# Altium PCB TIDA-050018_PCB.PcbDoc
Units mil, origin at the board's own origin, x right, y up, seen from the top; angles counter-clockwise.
Board outline 2547.53 x 1907.53 mil, 2 copper layers (Top Layer, Bottom Layer), stack 62 mil thick; 19 components, 10 nets, 73 pads, 3 vias.
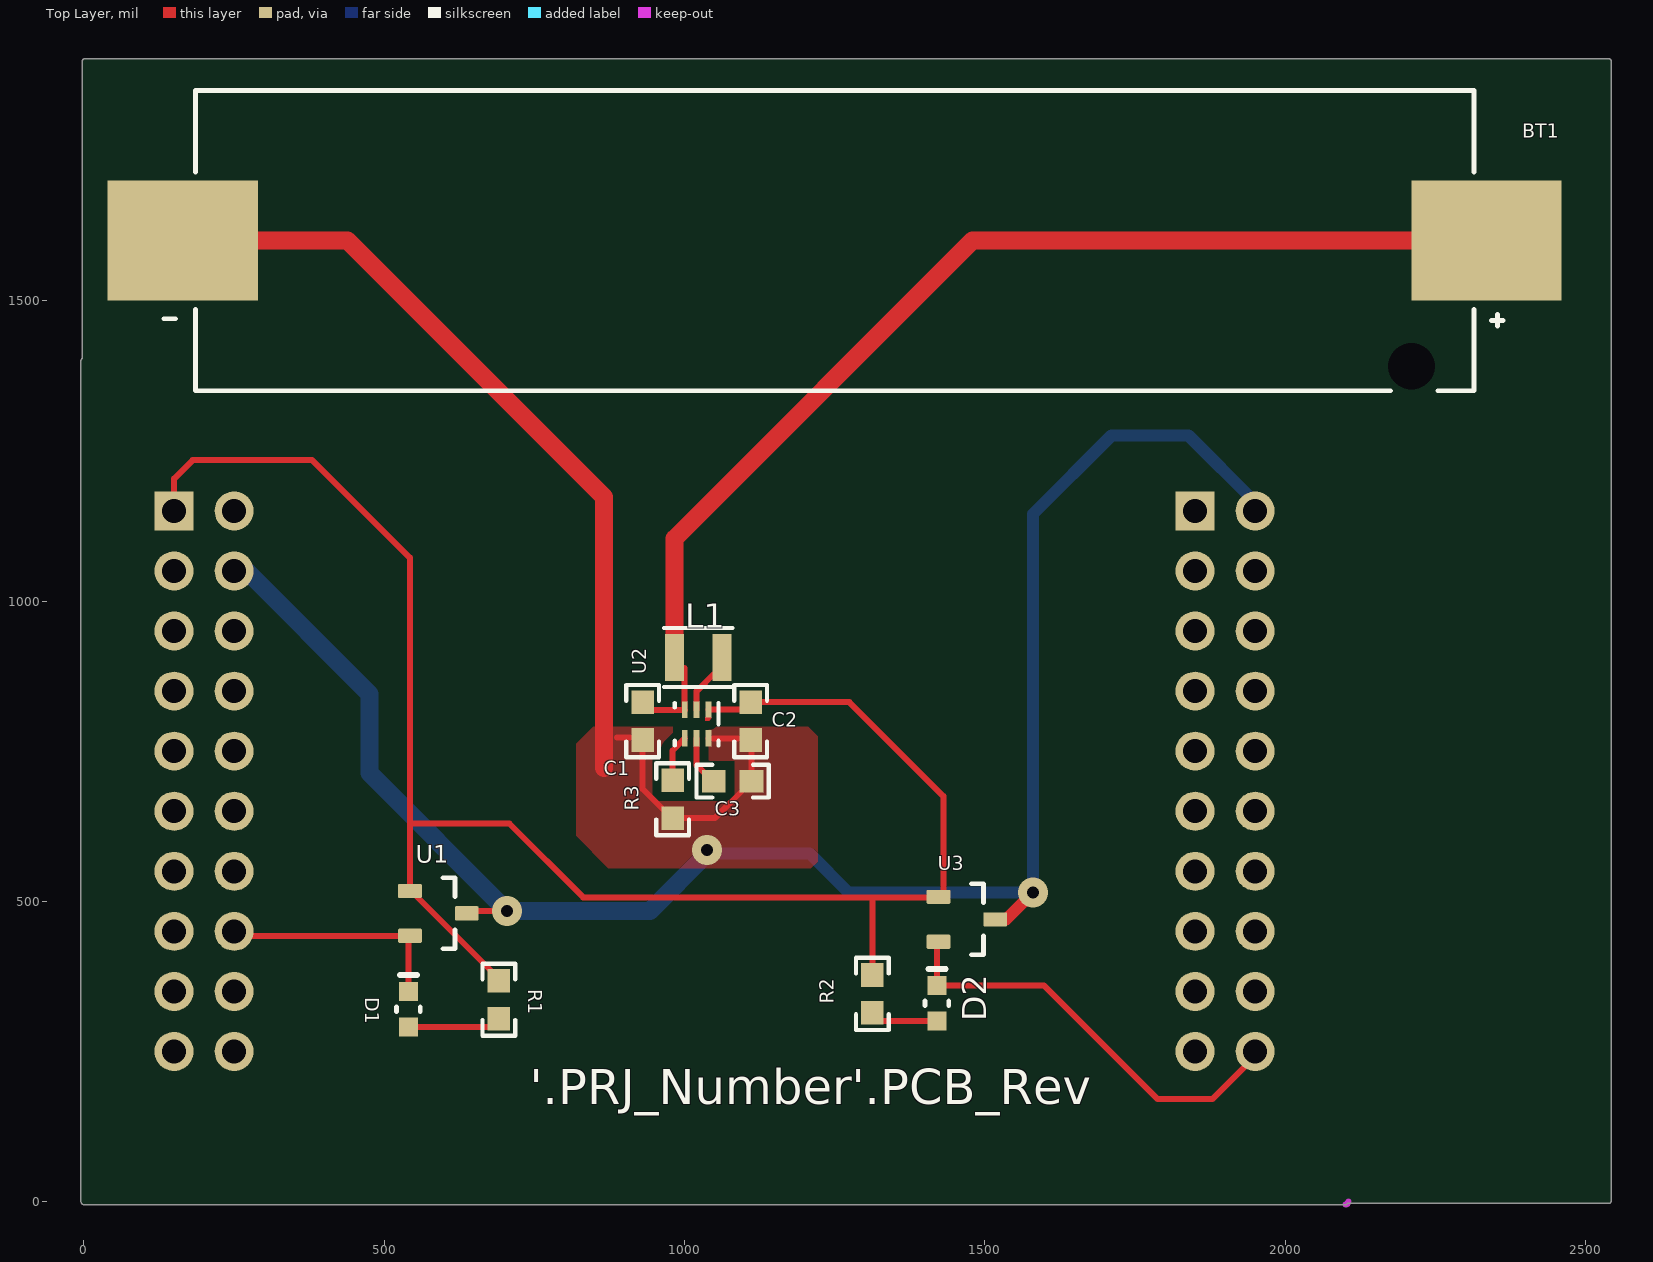
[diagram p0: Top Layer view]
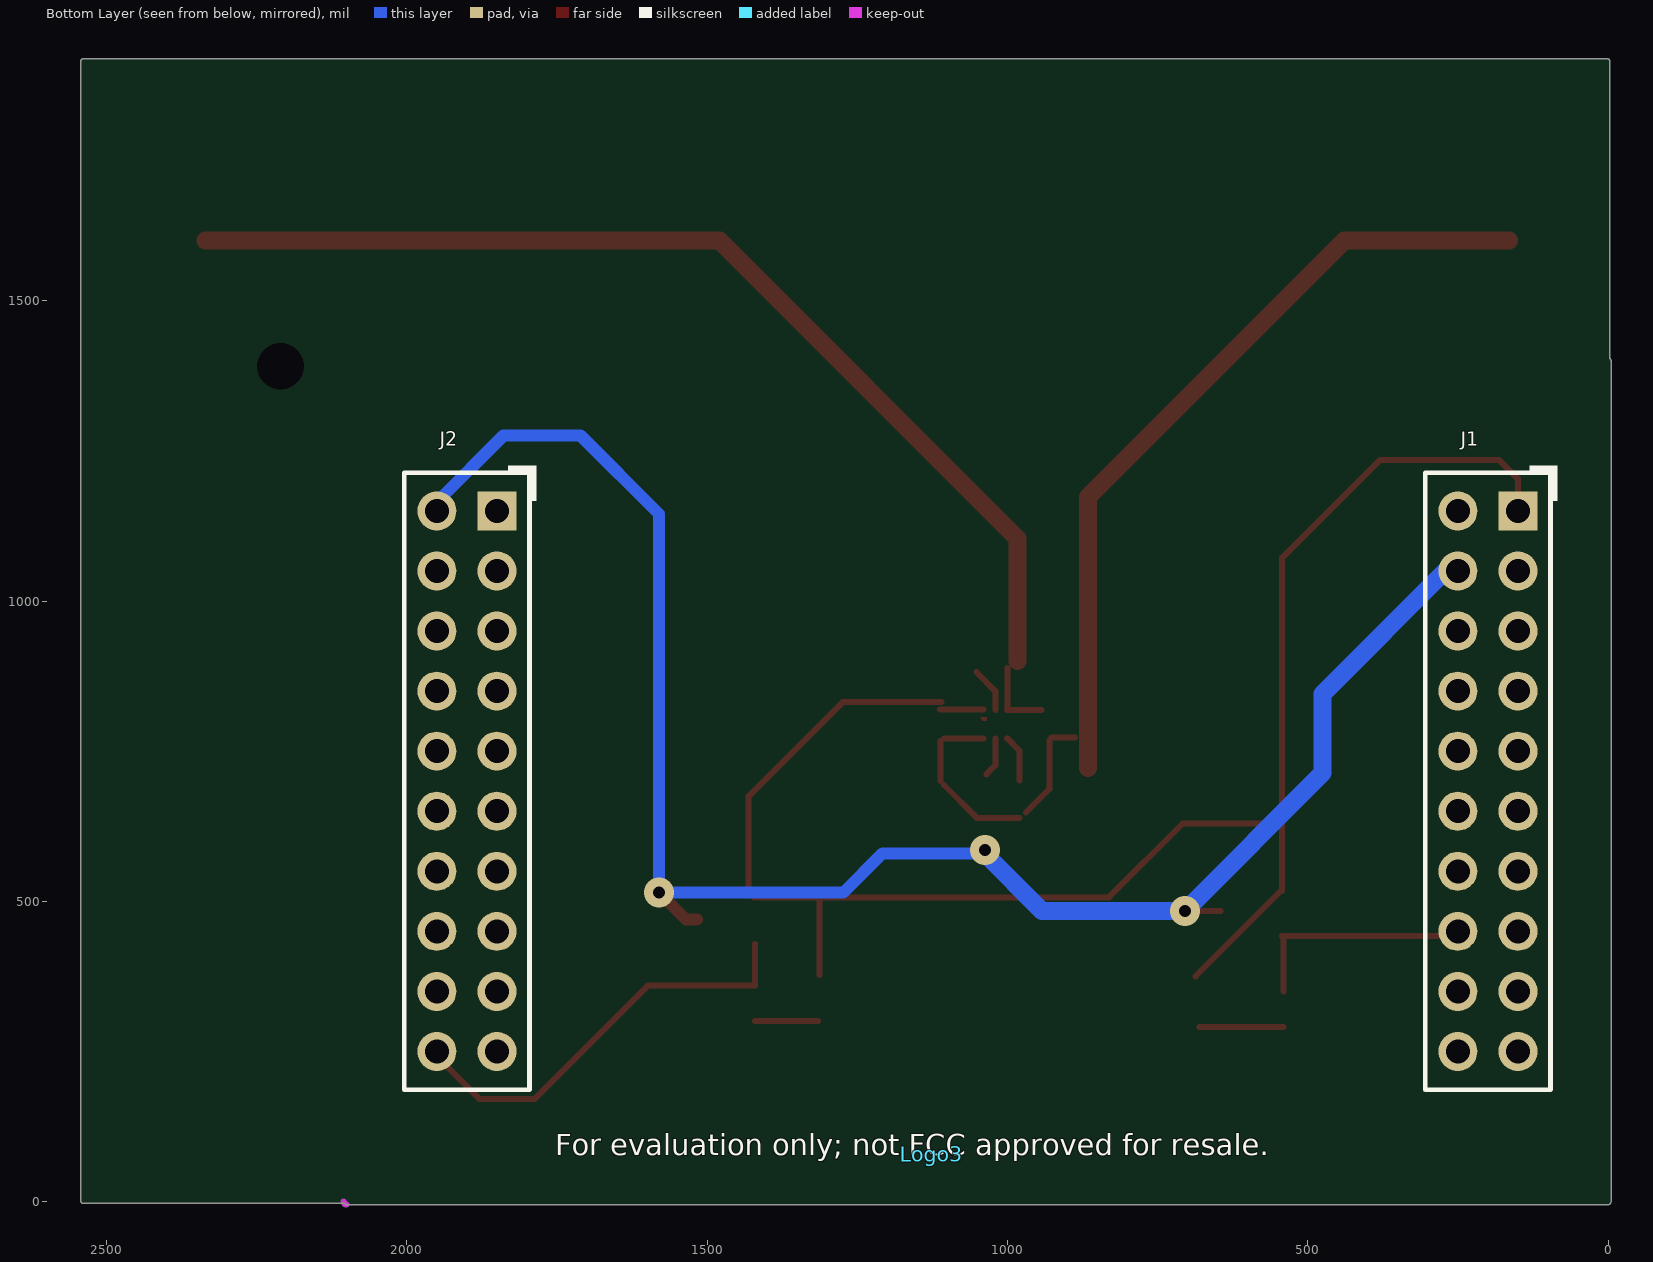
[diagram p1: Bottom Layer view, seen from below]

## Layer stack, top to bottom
Top Solder: solder mask 0.4, Solder Resist, Dk 3.5
Top Layer: signal copper 1.4
Dielectric1: core 59.2, FR-4, Dk 4.8
Bottom Layer: signal copper 1.4
Bottom Solder: solder mask 0.4, Solder Resist, Dk 3.5

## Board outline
-5.01,0 -5.01,1400 cw(c0,1400) -2.51,1404.34 -2.51,1900 cw(c0,1900) 0,1902.51 2540,1902.51 cw(c2540,1900) 2542.51,1900 2542.51,0 cw(c2540,0) 2540,-2.52 2104.34,-2.52 cw(c2100,0) 2100,-5.02 0,-5.02 cw(c0,0)

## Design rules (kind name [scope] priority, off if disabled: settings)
AcuteAngle [All] p1: minimum=4.50000000000000E+0001 checktracksonly=FALSE
AssemblyTestPointUsage [All] p1: valid=2
BoardOutlineClearance BoardOutlineClearance_MountingHoles [OnCopper and InComponentClass('Mounting Holes')] p1: gap=40 ignorepadtopadclearanceinfootprint=FALSE
BoardOutlineClearance BoardOutlineClearance_Poly [OnCopper and InPoly] p2: gap=25 ignorepadtopadclearanceinfootprint=FALSE
BoardOutlineClearance [OnCopper and Not InComponentClass('Logo') and not InComponentClass('FiducialMark') and not InRegion(1000,500,4000,800)] p3: gap=25 ignorepadtopadclearanceinfootprint=FALSE
Clearance Clearance_Keepouts [((IsTrack Or IsArc) And Not InPoly) And IsFree and IsKeepOut vs ((IsTrack Or IsArc) And Not InPoly) And IsFree and IsKeepOut] p1: gap=0 ignorepadtopadclearanceinfootprint=FALSE
Clearance Clearance_Poly [InPolygon] p2: gap=15 ignorepadtopadclearanceinfootprint=FALSE except(0: Arc-Hole Track-Hole SMDPad-Hole THPad-Hole Via-Hole Fill-Hole Poly-Hole Region-Hole Text-Hole; 10: THPad-Poly)
Clearance [All] p3: gap=3 ignorepadtopadclearanceinfootprint=FALSE
ComponentClearance ComponentClearance_MountingHoles_FiducialMarks [InComponentClass('Mounting Holes') vs InComponentClass('FiducialMark')] p1: gap=50 collisioncheckmode=3 verticalgap=10 showdistances=FALSE
ComponentClearance ComponentClearance_Shunt [InComponentClass('Header') vs InComponentClass('Shunt')] p2: gap=0 collisioncheckmode=3 verticalgap=0 showdistances=FALSE
ComponentClearance ComponentClearance_Logo [InComponentClass('Logo')] p3: gap=0 collisioncheckmode=3 verticalgap=0 showdistances=FALSE
ComponentClearance ComponentClearance_ScrewToNut [(HasFootprint('NY PMS 440 0025 PH')) vs (HasFootprint('Keystone_1902C'))] p4: gap=5 collisioncheckmode=3 verticalgap=10 showdistances=FALSE
ComponentClearance ComponentClearance_MountingHoles [InComponentClass('Mounting Holes')] p5: gap=250 collisioncheckmode=3 verticalgap=100000 showdistances=FALSE
ComponentClearance ComponentClearance_SmallPassives [HasFootprint('0201*') or HasFootprint('0402*') or HasFootprint('0508') or HasFootprint('0603*') or HasFootprint('0612') or HasFootprint('0805*') or HasFootprint('0815*') or HasFootprint('0830*') or HasFootprint('1206*') or HasFootprint('1210*') or HasFootprint('1808*') or HasFootprint('1812*') or HasFootprint('1825*') or HasFootprint('2010*') or HasFootprint('2220*') or HasFootprint('2225*') or HasFootprint('2512*') or HasFootprint('2728*') or HasFootprint('3518*') vs HasFootprint('0201*') or HasFootprint('0402*') or HasFootprint('0508') or HasFootprint('0603*') or HasFootprint('0612') or HasFootprint('0805*') or HasFootprint('0815*') or HasFootprint('0830*') or HasFootprint('1206*') or HasFootprint('1210*') or HasFootprint('1808*') or HasFootprint('1812*') or HasFootprint('1825*') or HasFootprint('2010*') or HasFootprint('2220*') or HasFootprint('2225*') or HasFootprint('2512*') or HasFootprint('2728*') or HasFootprint('3518*')] p6: gap=14.96 collisioncheckmode=3 verticalgap=10 showdistances=FALSE
ComponentClearance ComponentClearance_THtoSMT [IsThruComponent vs IsSMTComponent] p7: gap=40 collisioncheckmode=3 verticalgap=30 showdistances=FALSE
ComponentClearance ComponentClearance_THtoTH [IsThruComponent vs IsThruComponent] p8: gap=30 collisioncheckmode=3 verticalgap=30 showdistances=FALSE
ComponentClearance [All] p9: gap=30 collisioncheckmode=3 verticalgap=10 showdistances=FALSE
DiffPairsRouting [All] p1: maxlimit=100 minlimit=10 mostfreqgap=10 toplayer_minwidth=15 toplayer_maxwidth=15 toplayer_prefwidth=15 bottomlayer_minwidth=15 bottomlayer_maxwidth=15 bottomlayer_prefwidth=15 maxuncoupledlength=1000
FabricationTestPointUsage TestPointUsage [All] p1: valid=2 allowmultiple=FALSE
FabricationTestpoint Testpoint [All] p1: side=3 testpointundercomponent=TRUE minsize=40 maxsize=100 preferedsize=60 minholesize=0 maxholesize=40 preferedholesize=32 testpointgrid=1 allowsidetop=TRUE allowsidebottom=TRUE usegrid=TRUE gridtolerance=0.01
FanoutControl Fanout_LCC [IsLCC] p1: bgadir=Out bgaviamode=Centered fanoutstyle=Auto fanoutdirection=Alternating viagrid=1 // Fanout_LCC (Default Rule)
FanoutControl Fanout_BGA [IsBGA] p2: bgadir=Out bgaviamode=Centered fanoutstyle=Auto fanoutdirection=Alternating viagrid=1 // Fanout_BGA (Default Rule)
FanoutControl Fanout_Default [All] p4: bgadir=Out bgaviamode=Centered fanoutstyle=Auto fanoutdirection=Alternating viagrid=1 // Fanout_Default (Default Rule)
FanoutControl Fanout_Small [(CompPinCount < 5)] p5: bgadir=Out bgaviamode=Centered fanoutstyle=Auto fanoutdirection=OutThenIn viagrid=1 // Fanout_Small (Default Rule)
HoleSize [All] p1: absolutevalues=TRUE maxlimit=251 minlimit=7.87 maxpercent=80.000 minpercent=20.000
MinimumAnnularRing MinimumAnnularRing_ThermalPadVias [IsVia and InAnyComponent] p1: minimumring=5.91
MinimumAnnularRing [All] p2: minimumring=6
MinimumSolderMaskSliver MinimumSolderMaskSliver_Logo [InComponentClass('Logo') vs InComponentClass('Logo')] p1: minsoldermaskwidth=0.7
MinimumSolderMaskSliver [All] p2: minsoldermaskwidth=3.94
PlaneConnect [All] p1: planeconnectstyle=Relief reliefexpansion=10 reliefentries=4 reliefconductorwidth=10 reliefairgap=10
PolygonConnect PolygonConnect_1 [InThruComponent vs ispoly] p1: connectstyle=Relief reliefconductorwidth=15 reliefentries=4 polygonreliefangle="90 Angle" airgapwidth=15
PolygonConnect [All] p2: connectstyle=Direct reliefconductorwidth=10 reliefentries=4 polygonreliefangle="90 Angle" airgapwidth=10
RoutingVias ThermalPadVias [IsVia and InAnyComponent] p1: holewidth=7.87 width=19.68 viastyle="Through Hole" minholewidth=7.87 minwidth=19.68 maxholewidth=12.99 maxwidth=23.62
RoutingVias [All] p2: holewidth=10 width=26 viastyle="Through Hole" minholewidth=7.87 minwidth=22 maxholewidth=40 maxwidth=65
SilkToBoardRegionClearance [Not ((IsComment or IsDesignator) And (Hide <> 'False')) and not InRegion(1000,500,4000,800)] p1:
SilkToSilkClearance SilkToSilkClearance_Pb-FreeLogo [(HasFootprint('Pb-Free_Overlay_Medium') OR HasFootprint('Pb-Free_Overlay_Small')) vs (HasFootprint('Pb-Free_Overlay_Medium') OR HasFootprint('Pb-Free_Overlay_Small'))] p1: silktosilkclearance=0
SilkToSilkClearance [All] p2: silktosilkclearance=4
SilkToSolderMaskClearance SilkToComponentPadClearance [IsPad and InAnycomponent] p1: minsilkscreentomaskgap=5 clearancetoexposedcopper=TRUE
SilkToSolderMaskClearance "Silk to Solder Mask Opening" [All] p2: minsilkscreentomaskgap=4 clearancetoexposedcopper=FALSE
SolderMaskExpansion [All] p1: expansion=1.97
Width [All] p1: maxlimit=100 minlimit=7.8 preferedwidth=10 checkconnectedcopper=TRUE
15 further rules are at their usual default settings.

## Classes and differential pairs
component class AssemblyNote: ZZ1 ZZ2 ZZ3 ZZ4
component class TIDA-050018_Main: BT1 C1 C2 C3 D1 D2 J1 J2 L1 R1 R2 R3 U1 U2 U3
component class TIDA-050018_Hardware: !PCB1 Logo3 ZZ1 ZZ2 ZZ3

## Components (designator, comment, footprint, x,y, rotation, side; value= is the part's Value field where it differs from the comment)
BT1 "1020" Keystone_1020 1250,1600 r180 top
C1 "GRM188R60J106ME47D" 0603 930,800 r270 top value=10uF
C2 "GRM188R60J106ME47D" 0603 1110,800 r270 top value=10uF
C3 "GRM188R60J106ME47D" 0603 1080,700 r0 top value=10uF
D1 "LS L29K-G1J2-1-Z" "LS L29K_Red" 540,320 r90 top value=Red
D2 "LS L29K-G1J2-1-Z" "LS L29K_Red" 1420,330 r90 top value=Red
J1 "PPPC102LFBN-RC" Sullins_PPPC102LFBN-RC 200,700 r90 bottom
J2 "PPPC102LFBN-RC" Sullins_PPPC102LFBN-RC 1900,700 r90 bottom
L1 "1239AS-H-4R7M=P2" DFE252012C 1022.64,905.96 r0 top value=4.7uH
Logo3 "FCC disclaimer" FCC_disclaimer 1126.08,79.23 r180 bottom
R1 "RC0603FR-072K21L" 0603 690.7,336.25 r270 top value=2.21k
R2 "RC0603FR-072K21L" 0603 1312.77,345.96 r270 top value=2.21k
R3 "RC0603FR-072K21L" 0603 980,670 r90 top value=2.21k
U1 "DRV5032FBDBZR" DBZ0003A_N 590,480 r0 top
U2 "TPS610985DSER" DSE0006A 1020,795 r270 top
U3 "DRV5032FBDBZR" DBZ0003A_N 1470,470 r0 top
ZZ1 "These assemblies are ESD sensitive, ESD precautions shall be observed." AssemblyNote 70.98,3170.1 r0 top
ZZ2 "These assemblies must be clean and free from flux and all contaminants. Use of no clean flux is not acceptable." AssemblyNote 65.49,3032.88 r0 top
ZZ3 "These assemblies must comply with workmanship standards IPC-A-610 Class 2, unless otherwise specified." AssemblyNote 64.01,2902.93 r0 top

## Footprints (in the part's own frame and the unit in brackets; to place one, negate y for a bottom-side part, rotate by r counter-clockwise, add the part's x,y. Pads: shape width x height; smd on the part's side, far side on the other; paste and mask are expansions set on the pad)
0603 [mm] "0603 from SM-752 data"
  rect 1x0.95 smd: 1(-0.8,0) 2(0.8,0)
  silkscreen extent -1.52,-0.69 1.52,0.69, body extent -0.87,-0.47 0.87,0.47, height 1
AssemblyNote [mil] "Assembly Note"
DBZ0003A_N [mm] "SOT23, 3-Leads, Body 2.9x1.3mm, Pitch 0.95mm, Lead Span 2.4mm, IPC Medium Density"
  rrect17% 1x0.6 smd: 1(-1.2,0.95) 2(-1.2,-0.95) 3(1.2,0)
  silkscreen extent 0.2,-1.5 0.7,1.5, body extent -1.26,-1.46 1.26,1.46, height 0.98
DFE252012C [mm] "Toko"
  rect 0.8x2 smd: 1(-1,0) 2(1,0)
  silkscreen extent -1.45,-1.25 1.45,1.25, body extent -1.35,-1.1 1.35,1.1, height 1.2
DSE0006A [mm] "TI recommended land pattern"
  rect 0.66x0.25 smd: 1(-0.62,0.5)
  rect 0.7x0.25 smd: 2(-0.6,0) 3(-0.6,-0.5) 4(0.6,-0.5) 5(0.6,0) 6(0.6,0.5)
  Top Layer region: -0.3,0.625 -0.25,0.625 -0.15,0.525 -0.15,0.375 -0.3,0.375
  silkscreen extent -0.9,-0.92 0.9,0.92, body extent -0.77,-0.77 0.77,0.77, height 0.8
FCC_disclaimer [mil]
Keystone_1020 [mm] "HOLDER BATTERY AAA, SMT"
  rect 6.35x5.08 smd: 1(-27.57,0) 2(27.57,0)
  rect 0x0 hole 1.98 unplated: ALIGN(-24.395,5.31)
  silkscreen extent -28.28,-6.35 28.38,6.35, body extent -30.76,-6.35 30.75,6.35, height 11.27
"LS L29K_Red" [mm] "SMD, 2-Leads, Body 1.3x0.8mm"
  rect 0.8x0.8 smd paste-0.4: 1(-0.75,0) 2(0.75,0)
  silkscreen extent -0.1,-0.5 1.45,0.5, body extent -0.9,-0.45 0.9,0.45, height 0.67
Sullins_PPPC102LFBN-RC [mil] "Sullins"
  rect 65x65 hole 40: 1(450,-50)
  round 65 hole 40: 2(450,50) 3(350,-50) 4(350,50) 5(250,-50) 6(250,50) 7(150,-50) 8(150,50) 9(50,-50) 10(50,50) 11(-50,-50) 12(-50,50) 13(-150,-50) 14(-150,50) 15(-250,-50) 16(-250,50) 17(-350,-50) 18(-350,50) 19(-450,-50) 20(-450,50)
  silkscreen extent -514,-116 526,104, body extent -514,-104 514,104, height 335

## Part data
BT1: library part CMP-0003908-1, "HOLDER BATTERY AAA, SMT", Manufacturer=Keystone, Supplier Part Number 1=36-1020-ND
C1 C2 C3: library part CMP-0007303-5, "CAP, CERM, 10 uF, 6.3 V, +/- 20%, X5R, 0603", Cap_Case=0603, Manufacturer=MuRata, Supplier Part Number 1=490-3896-1-ND, TempCo=X5R, Tolerance_%=20%, Value1="0.009 ohm", Value2=6.3V, ValueDisplayed=10uF
D1 D2: library part CMP-0002902-1, "LED, Red, SMD", Color=Red, Manufacturer=OSRAM, Supplier Part Number 1=475-2506-1-ND, Value1=W, Value2=1.8V
J1 J2: library part CMP-0054642-1, "Receptacle, 100mil, 10x2, Gold, TH", Manufacturer="Sullins Connector Solutions", Supplier Part Number 1=S6106-ND
L1: library part CMP-0058899-1, "Inductor, Shielded, Ferrite, 4.7 uH, 1.3 A, 0.2 ohm, SMD", Manufacturer="MuRata Toko", PartNumber=1239AS-H-4R7M{}P2, Value1="0.2 ohm", Value2=1.3A, ValueDisplayed=4.7uH
Logo3: library part CMP-0074847-1, "FCC_disclaimer"
R1 R2 R3: library part CMP-0022984-5, "RES, 2.21 k, 1%, 0.1 W, 0603", Manufacturer=Yageo, Power_W=100mW, Supplier Part Number 1=311-2.21KHRCT-ND, TempCo="100 ppm/C", Tolerance_%=1%, Value2=0.1W, Value_Code=2k21, ValueDisplayed=2.21k
U1 U3: library part CMP-0013239-4, "Ultra-Low Power Digital-Switch Hall Effect Sensor, DBZ0003A (SOT-23-3)", Alternate Manufacturer="Texas Instruments"
U2: library part CMP-0074070-1, "Ultra-Low Quiescent Current Synchronous Boost with Integrated LDO/Load, DSE0006A (WSON-6)", Alternate Manufacturer="Texas Instruments", Alternate PartNumber=TPS610985DSET
ZZ1: library part CMP-0077236-1
ZZ2: library part CMP-0077237-1
ZZ3: library part CMP-0077238-1

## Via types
v1: diameter 50, hole 20, Top Layer to Bottom Layer, 3 vias

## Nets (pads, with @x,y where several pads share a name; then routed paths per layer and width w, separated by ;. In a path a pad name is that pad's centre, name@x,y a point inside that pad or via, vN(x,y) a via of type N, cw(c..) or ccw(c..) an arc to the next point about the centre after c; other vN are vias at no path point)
3.3V: C2.1 J1.1 R1.1 R2.1 U1.1 U2.1 U3.1 | length 2981
  Top Layer w10: J1.1 150,1203.6 181.08,1234.68 380.06,1234.68 542.5,1072.25 542.5,849.52 ; 542.76,851.6 542.76,629.6 ; R1.1@687.04,374.8 544.44,517.4 U1.1 542.76,629.6 ; U2.1 C2.1@1112.14,819.41 ; C2.1 1274.34,831.5 1430.73,675.11 U3.1@1430.73,508.99 ; R2.1 1312.77,503.69 ; 1351.1,506.15 U3.1@1421.85,506.15 ; 1365.17,506.5 831.28,506.5 708.17,629.6 542.76,629.6
GND: BT1.2 C1.2 C2.2 C3.2 J1.4 J2.2 R3.1 U1.3 U2.6 U3.3 | length 4716.6
  Top Layer w10: U1.3@645.18,484.2 v1(704.63,484.2) ; 887.41,772.9 C1.2@926.3,772.9 ; C1.2 930,687.27 R3.1@969.39,647.88 ; R3.1 1050.45,638.5 C3.2@1105.61,693.66 ; U2.6 C2.2@1105.8,771.38 ; C3.2 C2.2@1111.5,767.34
  Top Layer w20: U3.3 1535.34,470 v1@1577.18,511.83
  Top Layer w30: BT1.2 438.6,1600 865.71,1172.89 865.71,721.88
  Bottom Layer w20: v1@1039.36,579.73 1208.21,579.73 1273.43,514.51 v1(1579.86,514.51) 1579.86,1144.64 1710.78,1275.57 1838.96,1275.57 J2.2@1950.14,1164.39
  Bottom Layer w30: J1.4@266.83,1053.88 475.46,845.25 475.46,713.37 v1(704.63,484.2) 942.45,484.2 v1@1038.66,580.41
  other v1: 1037.28,585.19
HALL1: D1.2 J1.16 U1.2 | length 381.5
  Top Layer w10: J1.16@250.32,442.6 U1.2 ; D1.2 U1.2@540,438.63
HALL2: D2.2 J2.20 U3.2 | length 708.7
  Top Layer w10: U3.2@1420,429.23 D2.2 1598.53,359.53 1787.07,170.99 1879.16,170.99 J2.20@1951.1,242.93
NetBT1_1: BT1.1 C1.1 L1.1 U2.3 | length 1888.7
  Top Layer w10: C1.1@942.87,818.62 U2.3 1000,818.94 1000,888.5
  Top Layer w30: L1.1@983.54,900.19 983.54,1104.23 1479.31,1600 BT1.1
NetC3_1: C3.1 U2.5 | length 66.1
  Top Layer w10: U2.5 1020,726.57 C3.1@1035.07,711.5
NetD1_1: D1.1 R1.2 | length 140.4
  Top Layer w10: D1.1 R1.2@680.37,290.47
NetD2_1: D2.1 R2.2 | length 105
  Top Layer w10: R2.2@1315.02,300.47 D2.1
NetL1_2: L1.2 U2.2 | length 75.9
  Top Layer w10: U2.2 1020,850 L1.2@1051.5,881.5
NetR3_2: R3.2 U2.4 | length 78.3
  Top Layer w10: R3.2 980,751.06 U2.4
pads on no net: BT1.ALIGN J1.2 J1.3 J1.5 J1.6 J1.7 J1.8 J1.9 J1.10 J1.11 J1.12 J1.13 J1.14 J1.15 J1.17 J1.18 J1.19 J1.20 J2.1 J2.3 J2.4 J2.5 J2.6 J2.7 J2.8 J2.9 J2.10 J2.11 J2.12 J2.13 J2.14 J2.15 J2.16 J2.17 J2.18 J2.19

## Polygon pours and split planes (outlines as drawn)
GND on Top Layer "TOP_LAYER_GND_P002" (solid, remove dead copper, pour order 2): 1221.46,775.13 1205.64,790.96 848.02,790.96 819.46,762.41 819.46,608.95 873.27,555.14 1210.38,555.14 1221.46,566.22

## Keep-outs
Keep-Out Layer:
  lines w10: 2100,-5 ccw(c2100,0) 2105,0 cw(c2100,0) 2100,-5
  text ".Layer_Name" at 577,-858.49 h60

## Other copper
Top Layer:
  text ".Layer_Name" at 577,-858.49 h60
Bottom Layer:
  text ".Layer_Name" at 577,-858.49 h60

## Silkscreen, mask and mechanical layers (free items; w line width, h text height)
Top Overlay:
  text "'.PRJ_Number'.PCB_Rev" at 741.84,142.96 h100
  text ".Layer_Name" at 577,-858.49 h60
Bottom Overlay:
  text ".Layer_Name" at 577,-858.49 h60
Top Paste:
  text ".Layer_Name" at 577,-858.49 h60
Bottom Paste:
  text ".Layer_Name" at 577,-858.49 h60
Top Solder:
  text ".Layer_Name" at 577,-858.49 h60
  text ".Layer_Name" at 577,-858.49 h60
Bottom Solder:
  text ".Layer_Name" at 577,-858.49 h60
Drill Guide:
  text ".Layer_Name" at 577,-858.49 h60
M1 Board Outline:
  lines w5: 0,1400 0,1900 2540,1900 2540,0 2000,0
  lines w10: 0,1400 0,0 2100,0
  text ".Layer_Name" at 577,-858.49 h60
M2 Board Dimensions:
  rectangle: 125,-400 500,-275
  rectangle: 0,-275 125,-150
  lines w7: 0,-275 1000,-275 ; 125,-400 125,-150 ; 250,-400 250,-150 ; 500,-400 500,-150 ; 750,-400 750,-150 ; 0,-400 0,-150 1000,-150 1000,-400 0,-400
  text ".Layer_Name" at 577,-858.49 h60
M3 3D STEP Top:
  text ".Layer_Name" at 577,-858.49 h60
M4 3D STEP Bottom:
  text ".Layer_Name" at 577,-858.49 h60
M5 Assembly Top:
  lines w10: -292,-930.17 6308,-930.17 ; -292,-726.83 6310,-726.83 ; -292,-523.5 -292,-1133.5 3713,-1133.5 6310,-1133.5 6310,-523.5 -291.5,-523.5 -291.5,-1133.5 1284,-1133.5 ; 2173,-1133.5 2173,-523.5 ; 3440,-726.83 3440,-523.5 ; 4280,-726.83 4280,-523.5 ; 4902,-1140 4902,-937.17
  text "COMPONENTS MARKED 'DNP' SHOULD NOT BE POPULATED." at 1153.5,-318.5 h60
  text "ASSEMBLY VARIANT:" at 1153,-434 h60
  text ".VariantName" at 2189,-434 h60
  text "PCB VIEWED FROM TOP SIDE" at -228.5,-655.67 h60
  text "BOARD #:" at 2248,-655.67 h60
  text ".PRJ_Number" at 2793.5,-655.67 h60
  text "REV:" at 3638,-655.67 h60
  text ".PCB_Rev" at 3929.5,-655.67 h60
  text "SVN REV:" at 4476,-655.67 h60
  text ".VersionControl_RevNumber" at 4982,-655.67 h60
  text "TID #:" at 2248,-859 h60
  text ".TID" at 2793.5,-859 h60
  text "PLOT NAME =" at -228.5,-1064.34 h60
  text ".plot_File_Name" at 577,-1064.34 h60
  text "GENERATED    :" at 2250,-1064.34 h60
  text ".Print_Date" at 3119.5,-1064.34 h60
  text ".Print_Time" at 3848.5,-1064.34 h60
  text "TEXAS INSTRUMENTS" at 5113,-1064.34 h60
M6 Assembly Bottom:
  lines w10: -292.5,-727.33 6309.5,-727.33 ; -290.5,-930.67 6309.5,-930.67 ; 1115.5,-1140.5 1115.5,-937.67 ; 1737.5,-727.33 1737.5,-524 ; 2577.5,-727.33 2577.5,-524 ; 3844.5,-1134 3844.5,-524 ; 4733.5,-1134 6309,-1134 6309,-524 -292.5,-524 -292.5,-1134 2304.5,-1134 6309.5,-1134 6309.5,-524
  text "COMPONENTS MARKED 'DNP' SHOULD NOT BE POPULATED." at 6102,-318 h60
  text ".VariantName" at 5058,-434 h60
  text "ASSEMBLY VARIANT:" at 6097,-434 h60
  text ".VersionControl_RevNumber" at 1035.5,-656.17 h60
  text "SVN REV:" at 1541.5,-656.17 h60
  text ".PCB_Rev" at 2088,-656.17 h60
  text "REV:" at 2379.5,-656.17 h60
  text ".PRJ_Number" at 3224,-656.17 h60
  text "BOARD #:" at 3769.5,-656.17 h60
  text "PCB VIEWED FROM BOTTOM SIDE" at 6246,-656.17 h60
  text ".TID" at 3224,-859.5 h60
  text "TID #:" at 3769.5,-859.5 h60
  text "TEXAS INSTRUMENTS" at 904.5,-1064.84 h60
  text ".Print_Time" at 2169,-1064.84 h60
  text ".Print_Date" at 2898,-1064.84 h60
  text "GENERATED    :" at 3767.5,-1064.84 h60
  text ".plot_File_Name" at 5440.5,-1064.84 h60
  text "PLOT NAME =" at 6246,-1064.84 h60
M9 Title Sheet:
  drawing of 57 lines, arcs and shapes, not listed
  text "1" at 739.84,8036.5 h70
  text "2" at 3235.5,8036.5 h70
  text "3" at 5724.84,8036.5 h70
  text "4" at 8231.51,8036.5 h70
  text "5" at 10730.5,8036.5 h70
  text "6" at 13235.5,8036.5 h70
  text "A" at -416.5,6893.5 h70
  text "A" at 14383.5,6893.5 h70
  text "B" at -416.5,4513.5 h70
  text "B" at 14383.5,4513.5 h70
  text "C" at -416.5,2138.5 h70
  text "C" at 14383.5,2138.5 h70
  text "PROJECT TITLE:" at 11343.5,277.5 h45
  text ".PRJ_Title" at 11393.5,144.17 h70
  text "DESIGNED FOR:" at 11343.5,-23.5 h45
  text ".PRJ_Customer" at 11393.5,-163.5 h70
  text "D" at -416.5,-231.5 h70
  text "D" at 14383.5,-231.5 h70
  text "FILE NAME:" at 11343.5,-323.5 h45
  text ".PCB_File_Name_No_Path" at 11393.5,-443.5 h70
  text "Texas Instruments (TI) and/or its licensors do not warrant the accuracy or completeness of this specification" at 6374,-605.34 h45
  text "ENGINEER:" at 11343.5,-613.5 h45
  text "LAYOUT BY:" at 12848.5,-613.5 h45
  text "or any information contained therein. TI and/or its licensors do not warrant that this design will meet" at 6329.01,-718 h45
  text ".PRJ_Engineer" at 11393.5,-768.49 h70
  text ".PCB_Layout" at 12899,-768.49 h70
  text "the specifications, will be suitable for your application or fit for any particular purpose, or will operate in" at 6329.01,-830.67 h45
  text ".Layer_Name" at 577,-858.49 h60
  text "ALTIUM DESIGNER VERSION:" at 12848.5,-923.5 h45
  text "an implementation. TI and/or its licensors do not warrant that the design is production worthy. You should" at 6329.01,-943.33 h45
  text "completely validate and test your design implementation to confirm the system functionality for your application." at 6374,-1056 h45
  text ".print_Scale" at 11393.5,-1056.83 h70
  text ".Application_BuildNumber" at 12899,-1056.83 h70
  text "1" at 739.84,-1263.5 h70
  text "2" at 3235.5,-1263.5 h70
  text "3" at 5724.84,-1263.5 h70
  text "4" at 8231.51,-1263.5 h70
  text "5" at 10730.5,-1263.5 h70
  text "6" at 13235.5,-1263.5 h70
M10 Fab Notes:
  drawing of 173 lines, arcs and shapes, not listed
  text "DESIGN INFORMATION" at 12378.02,6201 h60
  text "MIN. TRACK WIDTH:" at 11733.46,6021 h60
  text "8" at 12829.7,6021 h60
  text "MIL" at 12984.46,6021 h60
  text "MIN. CLEARANCE:" at 11733.46,5889 h60
  text "0.2" at 12769.7,5889 h60
  text "mm" at 12984.46,5889 h60
  text "MIN. VIA PAD SIZE:" at 11733.46,5757 h60
  text "22" at 12799.71,5757 h60
  text "MIL" at 12984.46,5757 h60
  text "0.05mm (2MIL)" at 12428.46,5615.29 h60
  text "MINIMUM ANNULAR RING" at 11404.23,5611 h60
  text "EXTERNAL" at 13136.46,5611 h60
  text "PER" at 11604.23,5493 h60
  text "IPC-D-275 CLASS 2 LEVEL C" at 11824.23,5493 h60
  text "MIL, HOLES" at 13312.46,5380.71 h60
  text "+/-" at 12920,5380 h60
  text "+/-" at 13774,5380 h60
  text "REGISTRATION TOLERANCES:" at 11404.23,5375 h60
  text "METAL" at 12604,5375 h60
  text "5" at 13180.2,5375 h60
  text "3" at 14013.2,5375 h60
  text "MIL" at 14129.46,5375 h60
  text "+/-" at 13774,5262 h60
  text "HOLE SIZE TOLERANCE (UNLESS OTHERWISE SPECIFIED):" at 11404.23,5257 h60
  text "3" at 14013.2,5257 h60
  text "MIL" at 14129.46,5257 h60
  text "MATERIAL:" at 11329.46,5047.54 h60
  text "FR-4 High Tg" at 12315.9,4907.21 h60
  text "FR-408" at 11750.46,4898.64 h60
  text "OTHER" at 13238.46,4898.64 h60
  text "X" at 13055.97,4896.67 h60
  text "FR-4" at 13583.01,4896.06 h60
  text "62 MIL (1.6mm) +/-10%" at 12070.56,4735.92 h60
  text "THICKNESS:" at 11404.23,4731.64 h60
  text "X" at 11942.4,4731.64 h60
  text "OTHER" at 13355.46,4731.64 h60
  text "TOLERANCE:" at 11404.23,4573.64 h60
  text "X" at 12243.53,4573.64 h60
  text "ANSI IPC-6012 TYPE 3 CLASS 2" at 12430.48,4573.64 h60
  text "OTHER +/-" at 12430.46,4417.64 h60
  text "BOW & TWIST:" at 11404.23,4260.64 h60
  text "X" at 12243.53,4260.64 h60
  text "ANSI IPC-6012 TYPE 3 CLASS 2" at 12430.48,4260.64 h60
  text "OTHER +/-" at 12430.46,4102.13 h60
  text "DRILLING:" at 11329.46,3963.64 h60
  text "REFERENCE:" at 11404.23,3846.64 h60
  text "X" at 12052.46,3846.64 h60
  text "AS SHOWN" at 12239.46,3846.64 h60
  text "X" at 12953.46,3846.64 h60
  text "NC_DRILL FILES" at 13090.46,3846.64 h60
  text "PTH COPPER THICKNESS:" at 11404.23,3688.64 h60
  text "X" at 12534.46,3688.64 h60
  text "20-30 um" at 12671.46,3688.64 h60
  text "OTHER" at 13388.46,3688.64 h60
  text "BOARD FINISH:" at 11329.46,3529.64 h60
  text "SILKSCREEN:" at 11484.68,3411.64 h60
  text "X" at 12433.46,3411.64 h60
  text "TOP" at 12559.46,3411.64 h60
  text "X" at 12943.46,3411.64 h60
  text "BOTTOM" at 13070.46,3411.64 h60
  text "SILKSCREEN COLOR:" at 11484.68,3244.64 h60
  text "X" at 12432.42,3244.64 h60
  text "WHITE" at 12559.46,3244.64 h60
  text "OTHER" at 13070.46,3244.64 h60
  text "X" at 12563.42,3085.44 h60
  text "GREEN" at 12690.46,3085.44 h60
  text "OTHER" at 13308.46,3085.44 h60
  text "SOLDER RESIST COLOR:" at 11484.68,3074.64 h60
  text "X" at 12563.42,2915.44 h60
  text "MATTE" at 12690.46,2915.44 h60
  text "SEMI-GLOSS" at 13308,2914.8 h60
  text "IMMERSION GOLD (ENIG)" at 12390.46,2726.92 h60
  text "ENEPIG" at 13728,2723.64 h60
  text "SURFACE FINISH:" at 11329.46,2722.64 h60
  text "X" at 12203.51,2722.64 h60
  text "IMM. TIN/SILVER OR EQUIV" at 11659,2565.64 h60
  text "OTHER" at 13090.46,2565.64 h60
  text "ARRAY/PANEL:" at 11329.46,2386.64 h60
  text "CUT AND TRIM PER M1 BOARD OUTLINE" at 12390.46,2382.35 h60
  text "N.C. ROUTE" at 12390.46,2230.64 h60
  text "X" at 13069.46,2230.64 h60
  text "V. SCORE" at 13256.46,2230.64 h60
  text "CERTIFICATION:" at 11329.46,2093.64 h60
  text "MATERIALS AND WORKMANSHIP FOR ALL PCBS" at 12054.46,2093.64 h60
  text "TO MEET OR EXCEED THE REQUIREMENTS OF:" at 12054.46,1995.64 h60
  text "X" at 11680.96,1859.13 h60
  text "ANSI IPC-A-600F CLASS ->" at 11819.96,1859.13 h60
  text "X" at 13459.02,1859.13 h60
  text "2" at 13577.96,1859.14 h60
  text "1" at 13262.96,1857.64 h60
  text "3" at 13931.96,1857.64 h60
  text "X" at 12495.02,1699.64 h60
  text "RoHS" at 12631.96,1699.64 h60
  text "OTHER" at 13276.36,1699.64 h60
  text "PER ORDER" at 13673.42,1699.64 h60
  text "ALL BOARDS MUST MEET OR EXCEED UL94-V0 REQUIREMENTS." at 11357,1534 h60
  text "PCB MUST BEAR THE UL94V-0 UL REGISTERED MATERIAL ID NUMBER" at 11357,1414 h60
  text "ADDITIONAL REQUIREMENTS:" at 11329.46,1240.64 h60
  text "MICROSECTION:" at 11404.23,1125.64 h60
  text "YES" at 12309.96,1125.64 h60
  text "REQUIRED" at 13171.46,969.49 h60
  text "BARE BOARD ELEC. TEST:" at 11404.23,966.64 h60
  text "NONE" at 12709.96,966.64 h60
  text "X" at 13044.46,966.64 h60
  text "PER ORDER" at 13763.46,966.64 h60
  text ".Layer_Name" at 577,-858.49 h60
M11 Gerber Information:
  lines w10: -292,-930.17 6308,-930.17 ; -292,-726.83 6310,-726.83 ; -292,-523.5 -292,-1133.5 3713,-1133.5 6310,-1133.5 6310,-523.5 -291.5,-523.5 -291.5,-1133.5 1284,-1133.5 ; 2173,-1133.5 2173,-523.5 ; 3440,-726.83 3440,-523.5 ; 4280,-726.83 4280,-523.5 ; 4902,-1140 4902,-937.17
  text "ALL ARTWORK VIEWED FROM TOP SIDE" at -228.5,-655.67 h60
  text "BOARD #:" at 2248,-655.67 h60
  text ".PRJ_Number" at 2793.5,-655.67 h60
  text "REV:" at 3638,-655.67 h60
  text ".PCB_Rev" at 3929.5,-655.67 h60
  text "SVN REV:" at 4476,-655.67 h60
  text ".VersionControl_RevNumber" at 4982,-655.67 h60
  text "LAYER NAME =" at -228.5,-858.49 h60
  text "TID #:" at 2248,-859 h60
  text ".TID" at 2793.5,-859 h60
  text "PLOT NAME =" at -228.5,-1064.34 h60
  text ".plot_File_Name" at 577,-1064.34 h60
  text "GENERATED    :" at 2250,-1064.34 h60
  text ".Print_Date" at 3119.5,-1064.34 h60
  text ".Print_Time" at 3848.5,-1064.34 h60
  text "TEXAS INSTRUMENTS" at 5113,-1064.34 h60
M12 Stackup:
  drawing of 191 lines, arcs and shapes, not listed
  text "Layer" at 9797.84,7830 h60
  text "Name" at 10207.76,7830 h60
  text "Material" at 11137.5,7830 h60
  text "Thickness" at 11997.27,7830 h60
  text "Constant" at 12647.1,7830 h60
  text "Board Layer Stack" at 13216.96,7830 h60
  text "1" at 9797.84,7710 h60
  text "Top Overlay" at 10207.76,7710 h60
  text "2" at 9797.84,7590 h60
  text "Top Solder" at 10207.76,7590 h60
  text "Solder Resist" at 11137.5,7590 h60
  text "0.40mil" at 11997.27,7590 h60
  text "3.5" at 12647.1,7590 h60
  text "3" at 9797.84,7470 h60
  text "Top Layer" at 10207.76,7470 h60
  text "Copper" at 11137.5,7470 h60
  text "1.40mil" at 11997.27,7470 h60
  text "4" at 9797.84,7350 h60
  text "Dielectric1" at 10207.76,7350 h60
  text "FR-4" at 11137.5,7350 h60
  text "59.20mil" at 11997.27,7350 h60
  text "4.8" at 12647.1,7350 h60
  text "5" at 9797.84,7230 h60
  text "Bottom Layer" at 10207.76,7230 h60
  text "Copper" at 11137.5,7230 h60
  text "1.40mil" at 11997.27,7230 h60
  text "6" at 9797.84,7110 h60
  text "Bottom Solder" at 10207.76,7110 h60
  text "Solder Resist" at 11137.5,7110 h60
  text "0.40mil" at 11997.27,7110 h60
  text "3.5" at 12647.1,7110 h60
  text "7" at 9797.84,6990 h60
  text "Bottom Overlay" at 10207.76,6990 h60
  text ".Layer_Name" at 577,-858.49 h60
M13 Component Bodies Top:
  text ".Layer_Name" at 577,-858.49 h60
M14 Component Bodies Bottom:
  text ".Layer_Name" at 577,-858.49 h60
M15 Courtyards Top:
  text ".Layer_Name" at 577,-858.49 h60
M16 Courtyards Bottom:
  text ".Layer_Name" at 577,-858.49 h60
Drill Drawing:
  circle w10: c5363.8,3266.08 r27.66
  lines w10: 5336.14,2989.5 5391.46,2989.5 5391.46,3044.82 5336.14,3044.82 5336.14,2989.5 ; 5336.14,3169.28 5391.46,3169.28 5363.8,3113.96 5336.14,3169.28
  lines w12: 5286,2952.17 8518.76,2952.17 ; 5286,3325.54 8518.76,3325.54 ; 5624.17,2827.71 5624.17,3450 ; 5956.28,2827.71 5956.28,3450 ; 6593.29,2827.71 6593.29,3450 ; 6852.64,2827.71 6852.64,3450 ; 7228.06,2827.71 7228.06,3450 ; 7951.91,2827.71 7951.91,3450 ; 5286,2827.71 8518.76,2827.71 8518.76,3450 5286,3450 5286,2827.71
  text "Symbol" at 5360.68,3362.88 h72
  text "Quantity" at 5661.51,3362.88 h72
  text "Finished Hole Size" at 5993.62,3362.88 h72
  text "Plated" at 6630.62,3362.88 h72
  text "Hole Type" at 6889.98,3362.88 h72
  text "Drill Layer Pair" at 7265.4,3362.88 h72
  text "Hole Tolerance" at 7989.25,3362.88 h72
  text "1" at 5661.51,3238.42 h60
  text "77.95mil (1.980mm)" at 5993.62,3238.42 h60
  text "NPTH" at 6630.62,3238.42 h60
  text "Round" at 6889.98,3238.42 h60
  text "Top Layer - Bottom Layer" at 7265.4,3238.42 h60
  text "3" at 5661.51,3113.96 h60
  text "20.00mil (0.508mm)" at 5993.62,3113.96 h60
  text "PTH" at 6630.62,3113.96 h60
  text "Round" at 6889.98,3113.96 h60
  text "Top Layer - Bottom Layer" at 7265.4,3113.96 h60
  text "40" at 5661.51,2989.5 h60
  text "40.00mil (1.016mm)" at 5993.62,2989.5 h60
  text "PTH" at 6630.62,2989.5 h60
  text "Round" at 6889.98,2989.5 h60
  text "Top Layer - Bottom Layer" at 7265.4,2989.5 h60
  text "44 Total" at 5661.51,2865.04 h60
  text ".Layer_Name" at 577,-858.49 h60
M17 Embedded Cavity:
  text ".Layer_Name" at 577,-858.49 h60
M18 Embedded Assembly:
  text ".Layer_Name" at 577,-858.49 h60
M19 Embedded Keepout:
  text ".Layer_Name" at 577,-858.49 h60

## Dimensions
0,0 to -5.01,1400 on M2 Board Dimensions
2540,0 to -2.51,1900 on M2 Board Dimensions
0,-400 to 1000,-400 on M2 Board Dimensions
